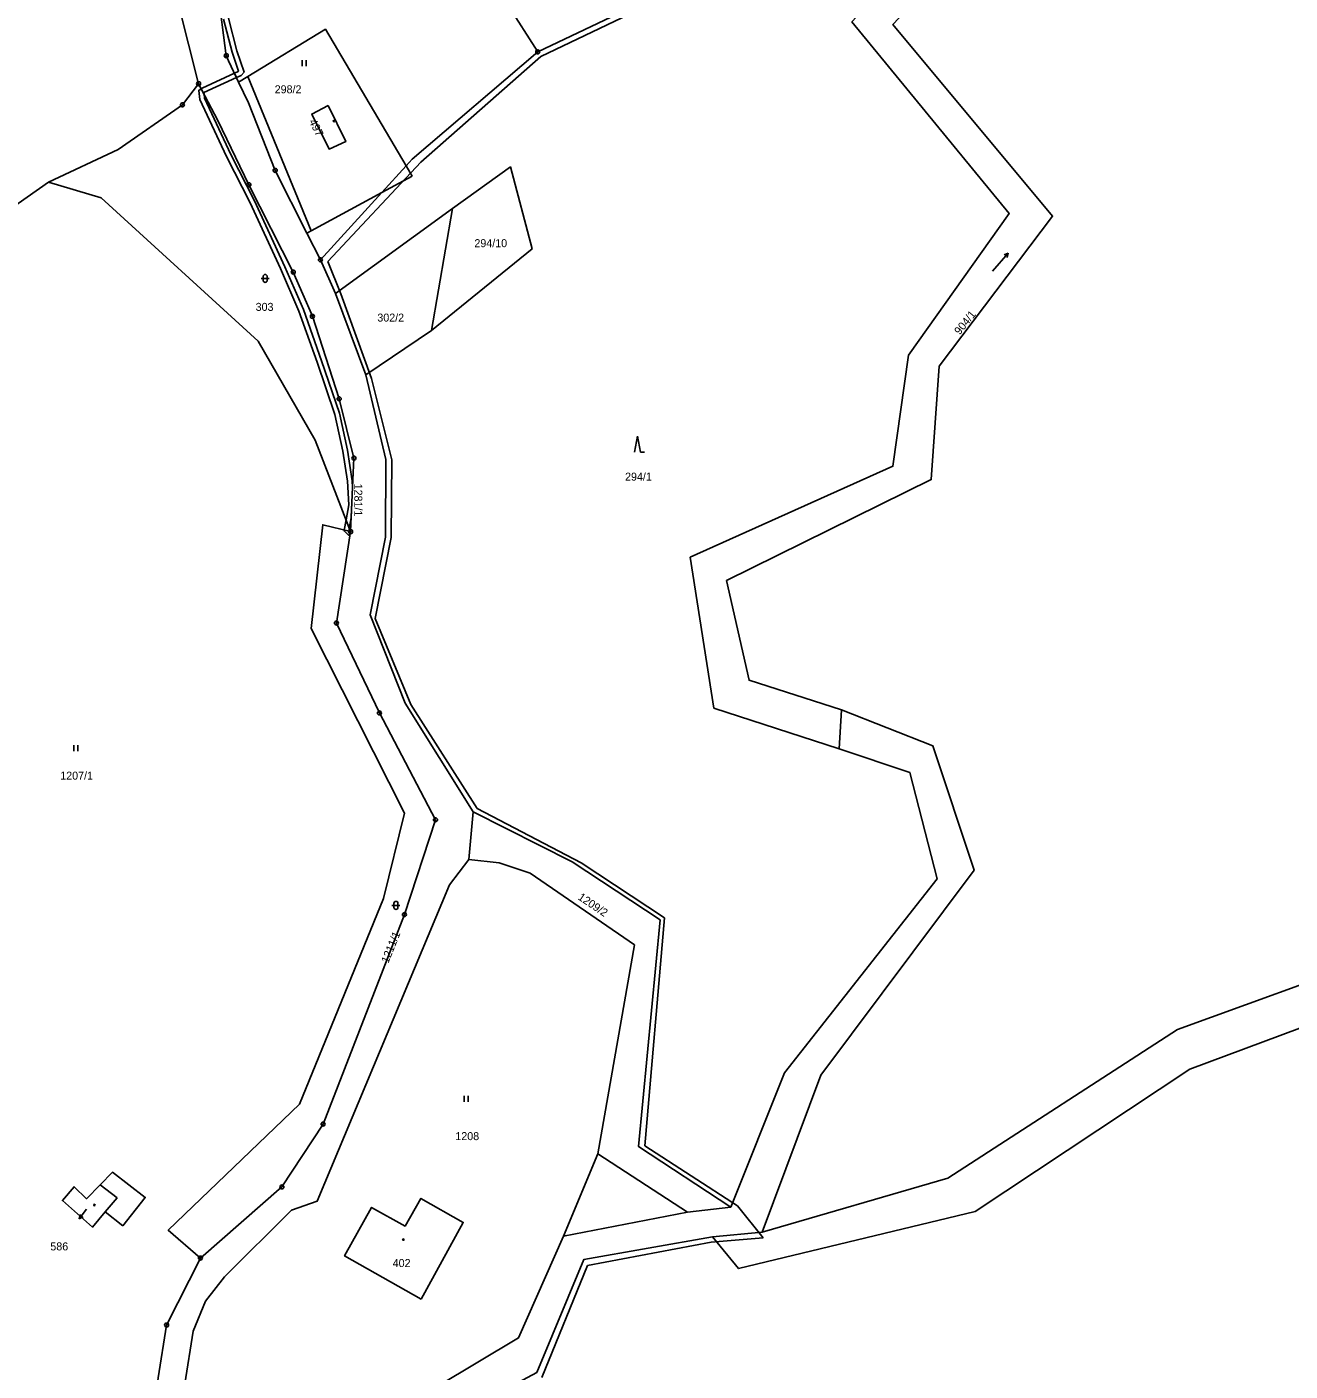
# Model space of a CAD drawing. Extents: x -745926 to -742978, y -968282 to -965689.
# Drawn here: x -745163.3 to -745005.4, y -967417.7 to -967249.8 of the extents above; entities that cross this region are included whole.
import ezdxf

# ---------------------------------------------------------------- set-up
doc = ezdxf.new("R2010")
doc.units = 0
for name, color, linetype in [('Hranice parcel', 7, 'Continuous'), ('Parcelní čísla', 7, 'Continuous'), ('Pop  PČ popisy', 7, 'Continuous'), ('Vnitřní kresba', 7, 'Continuous'), ('Věcná břemena k části', 7, 'Continuous'), ('Značky bodu BP', 7, 'Continuous'), ('Značky budov', 7, 'Continuous'), ('Značky kultur', 7, 'Continuous')]:
    doc.layers.add(name, color=color, linetype=linetype)

msp = doc.modelspace()

# ---------------------------------------------------------------- linework, layer by layer
at = {"layer": 'Hranice parcel'}
for p, q in [((-745141.85, -967256.86), (-745144.35, -967246.97)), ((-745171.21, -967276.58), (-745160.6, -967269.17)), ((-745124.73, -967283.07), (-745110.1, -967272.47)), ((-745110.1, -967272.47), (-745112.75, -967287.69)), ((-745126.62, -967278.87), (-745124.73, -967283.07)), ((-745124.73, -967283.07), (-745120.96, -967293.25)), ((-745112.75, -967287.69), (-745120.96, -967293.25)), ((-745061.5, -967335.1), (-745061.81, -967339.97)), ((-745107.53, -967347.86), (-745108.07, -967353.8)), ((-745080.73, -967397.89), (-745075.32, -967397.27)), ((-745071.43, -967400.4), (-745077.64, -967400.97))]:
    msp.add_line(p, q, dxfattribs=at)
for points in [[(-745009.63, -967189.18), (-745011.31, -967192.52), (-745031.56, -967224.61), (-745055.08, -967249.47), (-745035.12, -967273.42), (-745049.3, -967292.14), (-745050.29, -967306.34), (-745075.86, -967318.96), (-745073.05, -967331.4), (-745061.5, -967335.1)], [(-745061.81, -967339.97), (-745077.44, -967334.89), (-745080.41, -967316.03), (-745055.07, -967304.67), (-745053.14, -967290.77), (-745040.55, -967273.07), (-745060.19, -967249.14), (-745033.79, -967220.85), (-745030.03, -967214.38), (-745026.66, -967198.89)], [(-745099.47, -967252.88), (-745103.26, -967246.95), (-745078.63, -967236.51), (-745066.48, -967221.98)], [(-745062.35, -967223.93), (-745073.68, -967240.59), (-745099.47, -967252.88)], [(-745139.43, -967245.24), (-745138.39, -967253.36), (-745136.85, -967256.65)], [(-745136.85, -967256.65), (-745135.7, -967255.95), (-745125.99, -967250.06), (-745115.9, -967267.12)], [(-745099.47, -967252.88), (-745115.16, -967266.3), (-745115.9, -967267.12)], [(-745141.85, -967256.86), (-745143.87, -967259.5), (-745151.92, -967265.07), (-745160.6, -967269.17)], [(-745122.85, -967312.84), (-745122.43, -967303.65), (-745124.28, -967296.24), (-745127.63, -967285.93), (-745130.01, -967280.41), (-745135.56, -967269.48), (-745139.46, -967261.46), (-745141.85, -967256.86)], [(-745136.85, -967256.65), (-745135.63, -967259.27), (-745132.28, -967267.69), (-745128.32, -967275.52), (-745126.62, -967278.87)], [(-745125.64, -967259.57), (-745127.71, -967260.65), (-745125.55, -967265.03), (-745123.45, -967264.09), (-745125.64, -967259.57)], [(-745115.9, -967267.12), (-745118.94, -967270.45), (-745126.62, -967278.87)], [(-745110.1, -967272.47), (-745102.87, -967267.25), (-745100.16, -967277.51), (-745112.75, -967287.69)], [(-745160.6, -967269.17), (-745154.03, -967271.11), (-745134.4, -967289.03), (-745127.26, -967301.42), (-745122.85, -967312.84)], [(-745120.96, -967293.25), (-745118.43, -967303.83), (-745118.49, -967313.52), (-745120.39, -967323.25), (-745116.04, -967334.26), (-745107.53, -967347.86)], [(-744926.16, -967299.13), (-744934.65, -967318.87), (-744942.73, -967330.77), (-744959.62, -967353.03), (-744971.61, -967360.36), (-744994.47, -967365.99), (-745019.5, -967375.06), (-745048.21, -967393.63), (-745071.43, -967400.4)], [(-745141.62, -967403.61), (-745145.65, -967400.15), (-745129.25, -967384.37), (-745118.72, -967358.69), (-745116.12, -967348.04), (-745127.79, -967324.94), (-745126.33, -967311.97), (-745122.85, -967312.84)], [(-745141.62, -967403.61), (-745131.44, -967394.73), (-745126.29, -967386.88), (-745116.12, -967360.69), (-745112.24, -967348.85), (-745119.25, -967335.5), (-745124.62, -967324.26), (-745122.85, -967312.84)], [(-745071.43, -967400.4), (-745064.09, -967380.76), (-745044.9, -967355.15), (-745050.08, -967339.6), (-745061.5, -967335.1)], [(-745077.64, -967400.97), (-745074.37, -967404.94), (-745044.78, -967397.79), (-745017.98, -967380.02), (-744990.48, -967369.76), (-744968.34, -967364.05), (-744957.22, -967356.15), (-744941.62, -967338.34)], [(-745075.32, -967397.27), (-745068.64, -967380.47), (-745049.54, -967356.22), (-745052.94, -967342.94), (-745061.81, -967339.97)], [(-745107.53, -967347.86), (-745095.18, -967354.1), (-745084.18, -967361.37), (-745086.85, -967389.69), (-745075.32, -967397.27)], [(-745108.07, -967353.8), (-745110.51, -967356.97), (-745127.02, -967396.49), (-745130.22, -967397.65), (-745138.61, -967405.96), (-745140.97, -967409.02), (-745142.53, -967412.76), (-745143.59, -967419.35)], [(-745080.73, -967397.89), (-745091.96, -967390.6), (-745087.38, -967364.49), (-745100.4, -967355.53), (-745104.29, -967354.24), (-745108.07, -967353.8)], [(-745151.33, -967399.6), (-745153.51, -967397.84), (-745155.1, -967399.75), (-745158.87, -967396.43), (-745157.42, -967394.7), (-745155.88, -967396.2), (-745154.16, -967394.46), (-745152.6, -967392.9), (-745148.51, -967396.04), (-745151.33, -967399.6)], [(-745114.05, -967408.74), (-745108.78, -967399.16), (-745114.07, -967396.17), (-745116.04, -967399.62), (-745120.22, -967397.29), (-745123.6, -967403.35), (-745114.05, -967408.74)], [(-745122.19, -967425.76), (-745101.85, -967413.6), (-745096.23, -967400.9), (-745080.73, -967397.89)], [(-745251.9, -967595.65), (-745240.43, -967596.7), (-745232.19, -967584.41), (-745218.1, -967577.22), (-745215.17, -967570.19), (-745176.37, -967542.55), (-745169.29, -967533.31), (-745164.53, -967513.98), (-745157.12, -967504.6), (-745141.12, -967497.69), (-745139.48, -967483.22), (-745117.24, -967427.36), (-745099.56, -967417.91), (-745093.69, -967403.79), (-745077.64, -967400.97)], [(-745154.76, -967457.49), (-745150.02, -967447.3), (-745146.91, -967418.57), (-745145.85, -967411.99), (-745141.62, -967403.61)]]:
    msp.add_lwpolyline(points, dxfattribs=at)
at = {"layer": 'Pop  PČ popisy'}
for p, q in [((-745155.88, -967397.51), (-745156.76, -967398.72)), ((-745156.76, -967398.72), (-745156.67, -967398.17)), ((-745156.76, -967398.72), (-745156.27, -967398.47))]:
    msp.add_line(p, q, dxfattribs=at)
at = {"layer": 'Vnitřní kresba'}
for p, q in [((-745073.3, -967241.11), (-745099.07, -967253.46)), ((-745099.07, -967253.46), (-745114.09, -967266.68)), ((-745135.7, -967255.95), (-745127.79, -967275.24)), ((-745114.09, -967266.68), (-745125.69, -967279.1)), ((-745115.9, -967267.12), (-745115.15, -967268.4)), ((-745115.15, -967268.4), (-745118.94, -967270.45)), ((-745118.94, -967270.45), (-745127.79, -967275.24)), ((-745127.79, -967275.24), (-745128.32, -967275.52)), ((-745125.69, -967279.1), (-745124.08, -967283.12)), ((-745124.08, -967283.12), (-745120.22, -967293.68)), ((-745120.22, -967293.68), (-745117.68, -967303.86)), ((-745117.68, -967303.86), (-745117.77, -967313.57)), ((-745117.77, -967313.57), (-745119.77, -967323.68)), ((-745119.77, -967323.68), (-745115.34, -967334.43)), ((-745115.34, -967334.43), (-745107.05, -967347.44)), ((-745107.05, -967347.44), (-745094.05, -967354.22)), ((-745094.05, -967354.22), (-745083.62, -967361.12)), ((-745083.62, -967361.12), (-745086.07, -967389.59)), ((-745086.07, -967389.59), (-745074.49, -967397.11)), ((-745096.23, -967400.9), (-745091.96, -967390.6)), ((-745154.16, -967394.46), (-745152.04, -967396.08)), ((-745152.04, -967396.08), (-745153.51, -967397.84)), ((-745074.49, -967397.11), (-745071.29, -967401.07)), ((-745077.79, -967401.64), (-745093.24, -967404.56)), ((-745071.29, -967401.07), (-745077.79, -967401.64)), ((-745093.24, -967404.56), (-745098.94, -967418.54))]:
    msp.add_line(p, q, dxfattribs=at)
at = {"layer": 'Věcná břemena k části'}
msp.add_lwpolyline([(-745138.73, -967248.78), (-745137.64, -967252.93), (-745136.85, -967255.28), (-745136.9, -967255.34), (-745137.36, -967255.55), (-745137.11, -967256.1), (-745136.54, -967255.84), (-745136.17, -967255.42), (-745137.06, -967252.75), (-745138.13, -967248.68)], dxfattribs=at)
for points in [[(-745141.52, -967257.5), (-745141.16, -967258.18), (-745141.18, -967257.98), (-745137.11, -967256.1), (-745137.36, -967255.55), (-745141.42, -967257.43)], [(-745122.77, -967311.13), (-745122.6, -967307.3), (-745122.64, -967306.47), (-745123.24, -967302.66), (-745124.25, -967298.05), (-745126.47, -967291.48), (-745128.75, -967285.07), (-745131.07, -967279.73), (-745134.85, -967271.49), (-745137.83, -967265.71), (-745141.12, -967258.68), (-745141.16, -967258.18), (-745141.52, -967257.5), (-745141.82, -967257.69), (-745141.7, -967258.84), (-745138.37, -967265.97), (-745135.39, -967271.75), (-745131.61, -967279.97), (-745129.31, -967285.29), (-745127.03, -967291.68), (-745124.83, -967298.21), (-745123.82, -967302.78), (-745123.24, -967306.53), (-745123.08, -967309.5), (-745123.42, -967311.36), (-745123.65, -967312.64), (-745123.67, -967312.74), (-745123.09, -967313.32), (-745122.89, -967313.12), (-745122.85, -967312.84), (-745123.03, -967312.54), (-745123.01, -967312.43)]]:
    msp.add_lwpolyline(points, close=True, dxfattribs=at)
at = {"layer": 'Značky bodu BP'}
for centre, radius in [((-745138.39, -967253.36), 0.25), ((-745138.39, -967253.36), 0.0152), ((-745099.47, -967252.88), 0.25), ((-745099.47, -967252.88), 0.0152), ((-745141.85, -967256.86), 0.25), ((-745141.85, -967256.86), 0.0152), ((-745143.87, -967259.5), 0.25), ((-745143.87, -967259.5), 0.0152), ((-745132.28, -967267.69), 0.25), ((-745132.28, -967267.69), 0.0152), ((-745135.56, -967269.48), 0.25), ((-745135.56, -967269.48), 0.0152), ((-745126.62, -967278.87), 0.25), ((-745126.62, -967278.87), 0.0152), ((-745130.01, -967280.41), 0.25), ((-745130.01, -967280.41), 0.0152), ((-745127.63, -967285.93), 0.25), ((-745127.63, -967285.93), 0.0152), ((-745124.28, -967296.24), 0.25), ((-745124.28, -967296.24), 0.0152), ((-745122.43, -967303.65), 0.25), ((-745122.43, -967303.65), 0.0152), ((-745122.85, -967312.84), 0.25), ((-745122.85, -967312.84), 0.0152), ((-745124.62, -967324.26), 0.25), ((-745124.62, -967324.26), 0.0152), ((-745119.25, -967335.5), 0.25), ((-745119.25, -967335.5), 0.0152), ((-745112.24, -967348.85), 0.25), ((-745112.24, -967348.85), 0.0152), ((-745116.12, -967360.69), 0.25), ((-745116.12, -967360.69), 0.0152), ((-745126.29, -967386.88), 0.25), ((-745126.29, -967386.88), 0.0152), ((-745131.44, -967394.73), 0.25), ((-745131.44, -967394.73), 0.0152), ((-745141.62, -967403.61), 0.25), ((-745141.62, -967403.61), 0.0152), ((-745145.85, -967411.99), 0.25), ((-745145.85, -967411.99), 0.0152)]:
    msp.add_circle(centre, radius, dxfattribs=at)
at = {"layer": 'Značky budov'}
for centre in [(-745124.94, -967261.53), (-745154.87, -967396.99), (-745116.26, -967401.3)]:
    msp.add_circle(centre, 0.0875, dxfattribs=at)
at = {"layer": 'Značky kultur'}
for p, q in [((-745128.89, -967254.68), (-745128.89, -967253.93)), ((-745128.39, -967254.68), (-745128.39, -967253.93)), ((-745042.61, -967280.3), (-745040.65, -967278.03)), ((-745040.65, -967278.03), (-745041.16, -967278.24)), ((-745040.65, -967278.03), (-745040.78, -967278.57)), ((-745134.03, -967281.2), (-745133.03, -967281.2)), ((-745133.78, -967280.95), (-745133.78, -967281.45)), ((-745133.28, -967281.45), (-745133.28, -967280.95)), ((-745086.98, -967300.92), (-745087.35, -967302.92)), ((-745086.6, -967302.92), (-745086.98, -967300.92)), ((-745086.6, -967302.92), (-745086.11, -967302.92)), ((-745157.43, -967340.28), (-745157.43, -967339.53)), ((-745156.93, -967340.28), (-745156.93, -967339.53)), ((-745117.68, -967359.54), (-745116.68, -967359.54)), ((-745117.43, -967359.29), (-745117.43, -967359.79)), ((-745116.93, -967359.79), (-745116.93, -967359.29)), ((-745108.66, -967384.09), (-745108.66, -967383.34)), ((-745108.16, -967384.09), (-745108.16, -967383.34))]:
    msp.add_line(p, q, dxfattribs=at)
for centre, start, end in [((-745133.53, -967280.95), 0, 180), ((-745133.53, -967281.45), 180, 359.9879), ((-745117.18, -967359.29), 0, 180), ((-745117.18, -967359.79), 180, 359.9879)]:
    msp.add_arc(centre, 0.25, start, end, dxfattribs=at)

# ---------------------------------------------------------------- texts
at = {"layer": 'Parcelní čísla'}
for s, p in [('298/2', (-745132.34, -967258.06)), ('294/10', (-745107.38, -967277.29)), ('303', (-745134.72, -967285.25)), ('302/2', (-745119.51, -967286.59)), ('294/1', (-745088.55, -967306.47)), ('1207/1', (-745159.14, -967343.83)), ('1208', (-745109.76, -967388.88)), ('586', (-745160.38, -967402.66)), ('402', (-745117.59, -967404.74))]:
    msp.add_text(s, height=1, dxfattribs=at).set_placement(p)
for s, rotation, p in [('497', 297, (-745128.09, -967261.58)), ('904/1', 51, (-745046.73, -967288.32)), ('1281/1', 270, (-745122.39, -967306.84)), ('1209/2', 326, (-745094.53, -967358.73)), ('1211/1', 68, (-745118.14, -967366.84))]:
    msp.add_text(s, height=1, rotation=rotation, dxfattribs=at).set_placement(p)

doc.saveas('drawing.dxf')
